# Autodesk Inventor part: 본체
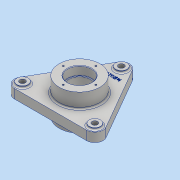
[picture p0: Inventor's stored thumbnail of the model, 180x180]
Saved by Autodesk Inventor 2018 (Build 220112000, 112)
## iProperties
Created: 2023-04
Part Number: 본체
Material: 알루미늄 6061
Document SubType Name: Modeling
Designer: home
Density: 2.7 g/cm^3
Appearance: 알루미늄 - 평지
Mass: 1221.77 g
Surface Area: 648.013 cm^2
Volume: 452.506 cm^3
Author: home
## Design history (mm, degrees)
sketch "스케치7"
  geometry: L1 (0, 0)-(-71.014, -41); L2 (0, 0)-(0, 57.274); L3 (0, 0)-(71.014, -41); L4 (-84.87, -33)-(-13.856, 90); L5 (-71.014, -57)-(71.014, -57); L6 (84.87, -33)-(13.856, 90); A1 r 82 centre (0, 0) between (0, 82) and (-71.014, -41); A2 r 16 centre (0, 82) between (13.856, 90) and (-13.856, 90); A3 r 16 centre (-71.014, -41) between (-84.87, -33) and (-71.014, -57); A4 r 16 centre (71.014, -41) between (71.014, -57) and (84.87, -33); 1 further point
  constraints: 12 end point, 9 point on circle, 4 centre point, 3 coincident, 3 tangent, 2 symmetric about line, 1 horizontal, 1 vertical
  dimensions: "d74" = 82 radius of A1; "d76" = 120 deg angle of L1 L2; "d77" = 120 deg angle of L2 L3
extrude "돌출5" new body sketch "스케치7" distance "d79" = 18; taper "d80" = 0 deg
sketch "스케치8"
  geometry: L1 (-71.014, -57)-(71.014, -57) reference; L2 (84.87, -33)-(13.856, 90) reference; L3 (-13.856, 90)-(-84.87, -33) reference; C1 r 11 at (0, 82); C2 r 11 at (-71.014, -41); C3 r 11 at (71.014, -41); A1 r 16 centre (71.014, -41) between (71.014, -57) and (84.87, -33) reference; A2 r 16 centre (0, 82) between (13.856, 90) and (-13.856, 90) reference; A3 r 16 centre (-71.014, -41) between (-84.87, -33) and (-71.014, -57) reference; 1 further point
  constraints: 3 centre point, 3 coincident
  dimensions: "d81" = 11 radius of C1; "d82" = 11 radius of C2; "d83" = 11 radius of C3
extrude "돌출6" join sketch "스케치8" distance "d84" = 4; taper "d85" = 0 deg
sketch "스케치9"
  geometry: L1 (71.014, -57)-(-71.014, -57) reference; L2 (13.856, 90)-(84.87, -33) reference; L3 (-84.87, -33)-(-13.856, 90) reference; C1 r 11 at (-71.014, -41) reference; A1 r 16 centre (71.014, -41) between (71.014, -57) and (84.87, -33) reference; A2 r 16 centre (0, 82) between (13.856, 90) and (-13.856, 90) reference; A3 r 16 centre (-71.014, -41) between (-84.87, -33) and (-71.014, -57) reference; 4 further points
  constraints: 2 coincident
hole "구멍7" sketch "스케치9" at (0, 82), (71.014, -41), (-71.014, -41) diameter "d86" = 11; stored, may be unused: countersink angle "d90" = 90 deg, drill point angle "d92" = 118 deg; dims "d87" = 6, "d88" = 47, "d89" = 17, "d91" = 70
node "작업 평면4"
sketch "스케치10"
  geometry: C1 r 45 at (0, 0); 1 further point
  constraints: 1 centre point, 1 coincident
  dimensions: "d94" = 45 radius of C1
extrude "돌출7" join sketch "스케치10" distance "d95" = 5; taper "d96" = 0 deg
sketch "스케치11"
  geometry: C1 r 45 at (0, 0) reference; C2 r 40 at (0, 0); 1 further point
  constraints: 1 centre point, 1 coincident
  dimensions: "d97" = 40 radius of C2
extrude "돌출8" join sketch "스케치11" distance "d98" = 23; taper "d99" = 0 deg; dims "d100" = 47, "d101" = 0
hole "구멍8" diameter "d104" = 42; stored, may be unused: countersink angle "d108" = 90 deg, drill point angle "d110" = 118 deg; dims "d102" = 10, "d103" = 10, "d105" = 6, "d106" = 47, "d107" = 17, "d109" = 70
hole "구멍9" diameter "d113" = 42; stored, may be unused: countersink angle "d117" = 90 deg, drill point angle "d119" = 118 deg; dims "d111" = 10, "d112" = 10, "d114" = 6, "d115" = 47, "d116" = 17, "d118" = 70
chamfer "모따기1" distance "d120" = 1; stored, may be unused: second distance "d121" = 2, angle "d122" = 45 deg
fillet "모깎기2" dims "d124" = 3
fillet "모깎기3" dims "d125" = 3
sketch "스케치12"
  geometry: L1 (0, 0)-(0, 32); 1 further point
  constraints: 2 end point, 1 coincident, 1 vertical
  dimensions: "d126" = 32 distance of L1.start L1.end
hole "구멍10" sketch "스케치12" at (0, 32) diameter "d127" = 3.242; stored, may be unused: countersink angle "d131" = 90 deg, drill point angle "d133" = 118 deg; dims "d128" = 8, "d129" = 47, "d130" = 17, "d132" = 10
node "작업 평면5"
sketch "스케치13"
  geometry: 2 further points
  constraints: 1 vertical alignment, 1 other
  dimensions: "d137" = 60 distance of point (0, 60) point (0, 0)
feature "엠보싱1" sketch "스케치13" dims "d82" = 11, "d138" = 0.5, "d139" = 0
fillet "모깎기4" dims "d140" = 0.6
fillet "모깎기5" dims "d141" = 0.6
node "솔리드2"
pattern_circular "원형 패턴1" dims angle "d135" = 360 deg
mirror "미러1"
node "투영된 루프5"
node "투영된 루프6"
node "투영된 루프7"
other parameters: "d75" = 16, "d78" = 16, "d93" = 5
